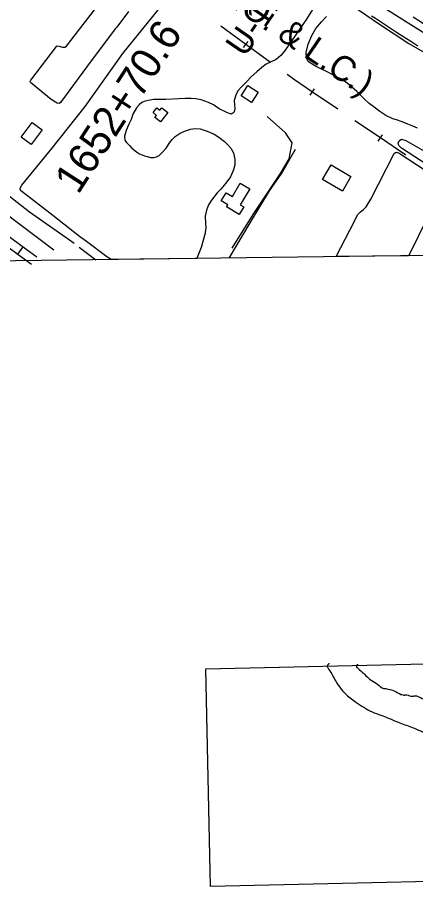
# Model space of a CAD drawing. Extents: x 3734862 to 3772949, y 391520 to 417239.
# Drawn here: x 3758594 to 3759905, y 395044 to 397909 of the extents above; entities that cross this region are included whole.
import ezdxf

# ---------------------------------------------------------------- set-up
doc = ezdxf.new("R2010")
doc.units = 0
for name, color, linetype in [('V-ANNO-NPLT', 7, 'Continuous'), ('V-BLDG-OTLN', 7, 'Continuous'), ('V-FLOD-BASE', 7, 'Continuous'), ('V-GRID-FRAM', 7, 'Continuous'), ('V-LEVE-TOET', 7, 'Continuous'), ('V-RAIL-IDEN', 7, 'Continuous'), ('V-RAIL-TRAK', 7, 'Continuous'), ('V-RIVR-EDGE', 7, 'Continuous'), ('V-RIVR-RANG-IDEN', 7, 'Continuous'), ('V-ROAD-CNTR', 7, 'Continuous'), ('V-SITE-VEGE', 7, 'Continuous'), ('V-SURV-IDEN', 7, 'Continuous'), ('V-SURV-LINE', 7, 'Continuous'), ('V-TOPO-SHOR', 7, 'Continuous')]:
    doc.layers.add(name, color=color, linetype=linetype)

msp = doc.modelspace()

# ---------------------------------------------------------------- linework, layer by layer
at = {"layer": 'V-ANNO-NPLT'}
for points in [[(3759229.9, 395044.4), (3759213.9, 395762.4), (3760468.2, 395790.9), (3760484.8, 395072.9)], [(3760484.8, 395072.9), (3759229.9, 395044.4)]]:
    msp.add_lwpolyline(points, dxfattribs=at)
for points in [[(3759613.6, 395771.7), (3759613.5, 395771.5), (3759614.4, 395768.6), (3759616.7, 395764.5), (3759628.7, 395745.7)], [(3759619.7, 395780.6), (3759619.6, 395778.6), (3759617.3, 395776.3), (3759615.2, 395774.6), (3759614.1, 395772.8), (3759613.6, 395771.7)], [(3759711.1, 395773.8), (3759710.8, 395773.6), (3759709.6, 395772.4), (3759709.9, 395770.6), (3759710.6, 395768.7), (3759711.5, 395767.1), (3759712.4, 395766.2)], [(3759713.9, 395777.5), (3759714.2, 395776.4), (3759713.8, 395775.7), (3759712.2, 395774.5), (3759711.1, 395773.8)], [(3759628.7, 395745.7), (3759651, 395707.3), (3759668.8, 395684.9), (3759702.3, 395656.6), (3759753.9, 395623.4)], [(3759712.1, 395766.5), (3759729, 395751.6), (3759745.8, 395735.6), (3759753.3, 395728.7), (3759775.6, 395715.1), (3759794.7, 395699.6), (3759799.7, 395697.8), (3759806.7, 395697), (3759815, 395695.7), (3759856.7, 395678.1)], [(3759856.7, 395678.1), (3759863.7, 395676.3), (3759869.7, 395675.9), (3759872.4, 395676.4), (3759889.1, 395672.4), (3759893.7, 395672), (3759898.3, 395672.5), (3759902.5, 395673), (3759907.6, 395673.1), (3759915.4, 395670.4), (3759939.1, 395661.9), (3759944.6, 395661.9), (3759953.9, 395658.3), (3759982.6, 395646.6)], [(3759753.9, 395623.4), (3759784.5, 395611.7), (3759797, 395607.2), (3759818.3, 395598.7), (3759852.6, 395584.2), (3759896.7, 395568.1), (3759932.4, 395552.3)]]:
    msp.add_spline(points, degree=3, dxfattribs=at)
at = {"layer": 'V-BLDG-OTLN'}
for points in [[(3759386.6, 397662.8), (3759364.8, 397628.6), (3759330.6, 397650.4), (3759352.4, 397684.5)], [(3759089.1, 397595.4), (3759065, 397564.8), (3759046.5, 397579.4), (3759052.1, 397586.4), (3759040.6, 397595.5), (3759053, 397611.2), (3759063, 397603.4), (3759069.1, 397611.1)], [(3758675.3, 397538.6), (3758639, 397489.9), (3758606.4, 397514.3), (3758642.7, 397563)], [(3759664.4, 397336.8), (3759598.6, 397374.9), (3759626.5, 397423.1), (3759692.3, 397384.9)], [(3759359, 397344.2), (3759327.9, 397291.9), (3759339.2, 397285.2), (3759324.3, 397260.2), (3759282.8, 397284.8), (3759287.1, 397292), (3759265.2, 397305), (3759280.9, 397331.5), (3759301.9, 397319), (3759327.9, 397362.7)]]:
    msp.add_lwpolyline(points, close=True, dxfattribs=at)
at = {"layer": 'V-FLOD-BASE'}
msp.add_lwpolyline([(3759946.6, 397878.8), (3759896.5, 397909.9)], dxfattribs=at)
at = {"layer": 'V-GRID-FRAM'}
msp.add_lwpolyline([(3738832.3, 415033.8), (3770599.2, 415447.4), (3770843.8, 397266.6), (3739061.1, 396852.8), (3738832.3, 415033.8)], dxfattribs=at)
at = {"layer": 'V-LEVE-TOET'}
msp.add_lwpolyline([(3759912.9, 397814.7), (3759889.3, 397829.4), (3759865.8, 397844.3), (3759842.4, 397859.4), (3759819.2, 397874.7), (3759796, 397890.1), (3759773, 397905.7), (3759759.6, 397913.2)], dxfattribs=at)
at = {"layer": 'V-RAIL-TRAK'}
for points in [[(3759345.8, 397820.3), (3759264.1, 397880.1)], [(3759338.5, 397810.2), (3759353.2, 397830.4)], [(3759427.6, 397760.6), (3759345.8, 397820.3)], [(3759565.4, 397663.2), (3759503.2, 397705.3), (3759482, 397720.7)], [(3759558.4, 397652.9), (3759572.4, 397673.6)], [(3759649.3, 397606.5), (3759565.4, 397663.2)], [(3759789.1, 397512.1), (3759705.2, 397568.8)], [(3759782.1, 397501.7), (3759796.1, 397522.4)], [(3759873, 397455.4), (3759869.1, 397458), (3759789.1, 397512.1)]]:
    msp.add_lwpolyline(points, dxfattribs=at)
at = {"layer": 'V-RIVR-EDGE'}
for points in [[(3755702.1, 404495.3), (3755757.2, 404470.8), (3755793.3, 404451.2), (3755852.5, 404424.4), (3755881.4, 404415.7), (3755906.2, 404404.4), (3755920.2, 404395.8), (3755948.7, 404379.4), (3755958.2, 404378.9), (3755969, 404378), (3755990.7, 404368.5), (3756022.8, 404350.3), (3756054.8, 404336.6), (3756079.7, 404323), (3756103.6, 404309.4), (3756144.2, 404288), (3756167.7, 404269), (3756188.9, 404253.6), (3756231.4, 404233.1), (3756271.6, 404217.2), (3756299.1, 404203.1), (3756403, 404163.5), (3756460.4, 404140.3), (3756508.7, 404114.9), (3756530.8, 404104), (3756588.2, 404078), (3756639.2, 404052.1), (3756694.3, 404019.5), (3756726.8, 403998.1), (3756735.8, 403989.1), (3756740.3, 403979.6), (3756740.3, 403973.2), (3756740.7, 403967.8), (3756747.5, 403960.5), (3756759.7, 403953.7), (3756786.3, 403941.5), (3756814.3, 403929.2), (3756864.5, 403904.6), (3756889.3, 403896), (3756899.7, 403897.3), (3756908.3, 403901.8), (3756919.2, 403901.3), (3756933.2, 403894.1), (3756945.8, 403892.7), (3756956.2, 403893.1), (3756962.1, 403897.2), (3756970.7, 403896.7), (3756978.4, 403894.4), (3756992.4, 403894.8), (3757002.8, 403897.5), (3757019.1, 403901.5), (3757027.7, 403901.5), (3757034, 403901.1), (3757036.3, 403896.5), (3757036.7, 403891.1), (3757038.5, 403883.4), (3757046.6, 403874.3), (3757060.6, 403866.2), (3757076.4, 403853.9), (3757104.4, 403831.2), (3757122.4, 403816.7), (3757145.5, 403804.5), (3757165.3, 403796.7), (3757181.6, 403787.2), (3757194.2, 403777.7), (3757213.6, 403765.4), (3757229.9, 403756.3), (3757251.6, 403745.9), (3757266.5, 403741.3), (3757283.2, 403734.5), (3757308.9, 403720.9), (3757360.4, 403694.1), (3757393.8, 403670.9), (3757430, 403657.3), (3757461.6, 403645.4), (3757505.4, 403628.1), (3757548.3, 403610.4), (3757591.7, 403587.2), (3757649.5, 403552.3), (3757711.8, 403512.8), (3757753.8, 403493.2), (3757766.9, 403487.8), (3757773.2, 403487.8), (3757785.9, 403494.1), (3757794.5, 403494), (3757803.5, 403489.5), (3757807.1, 403480.9), (3757810.6, 403456), (3757814.2, 403447.9), (3757826.4, 403437), (3757854.4, 403422.9), (3757930.3, 403373.9), (3757975.8, 403342.6), (3758005.2, 403323.5), (3758062.1, 403286.7), (3758092.3, 403263.6), (3758175.8, 403209.6), (3758234.5, 403169.2), (3758283.7, 403133.8), (3758328.8, 403103.4), (3758399.2, 403041.7), (3758421.8, 403023.1), (3758438.1, 403017.7), (3758463.8, 403017.6), (3758491.4, 403026.1), (3758504.5, 403022), (3758513.6, 403014.3), (3758514, 403006.2), (3758499.9, 402997.2), (3758498.1, 402989.9), (3758502.2, 402978.2), (3758510.7, 402969.6), (3758522, 402962.8), (3758545, 402948.7), (3758582.1, 402926.9), (3758650.2, 402878.8), (3758697.6, 402840.7), (3758721.5, 402820.3), (3758740.9, 402809.4), (3758782, 402784.9), (3758831.2, 402755.4), (3758902.1, 402711.8), (3758960.4, 402675.5), (3759018.6, 402634.6), (3759069.6, 402599.7), (3759134.6, 402553.4), (3759185.6, 402508.1), (3759223.5, 402478.1), (3759262.3, 402448.2), (3759321.4, 402402.4), (3759371.5, 402366.1), (3759431.5, 402323.4), (3759463.6, 402300.3), (3759488.9, 402281.7), (3759576.9, 402222.7), (3759627, 402186.8), (3759672.1, 402153.7), (3759778.2, 402087.4), (3759832.8, 402050.7), (3759873, 402019.4), (3759909.5, 401989.4), (3760050.8, 401883.7), (3760100, 401850.2), (3760145.6, 401819.3), (3760185.8, 401788), (3760211.9, 401766.7), (3760254.8, 401734.5), (3760285.5, 401709.1), (3760303.1, 401700.5), (3760325.3, 401691.4), (3760352.8, 401671.4), (3760391.1, 401641), (3760430.4, 401612), (3760461.6, 401590.2), (3760536.9, 401543), (3760583, 401510.8), (3760602.8, 401495.8), (3760629, 401477.2), (3760672.4, 401449.5), (3760711.2, 401426.8), (3760818.6, 401347.8), (3760872.3, 401310.6), (3760925.6, 401271.6), (3760948.6, 401251.7), (3761039.8, 401181.8), (3761107, 401135.5), (3761151.7, 401104.7), (3761172.9, 401093.3), (3761186, 401090.6), (3761199.2, 401092.8), (3761219.5, 401099.1), (3761228.1, 401099.5), (3761233.5, 401095.4), (3761236.7, 401087.7), (3761236.6, 401077.8), (3761228.5, 401063.8), (3761223, 401057.5), (3761223, 401049.3), (3761228.9, 401039.4), (3761242.4, 401026.7), (3761254.1, 401021.7), (3761266.8, 401018.5), (3761292.5, 401001.7), (3761317.3, 400980.4), (3761342.1, 400955.4), (3761463.1, 400853.4), (3761510, 400812.1), (3761550.2, 400777.7), (3761585.3, 400746.8), (3761681.5, 400674.3), (3761756.4, 400618.9), (3761817.8, 400572.2), (3761878.3, 400530.4), (3761996.5, 400436.5), (3762057.4, 400389.8), (3762104.8, 400352.6), (3762156.3, 400313.2), (3762204.5, 400277.3), (3762245.2, 400247.8), (3762291.6, 400210.2), (3762325.9, 400182.1), (3762356.2, 400159.8), (3762404, 400123.6), (3762432.9, 400101.3), (3762455.5, 400091.3), (3762473.5, 400075.9), (3762512.3, 400044.2), (3762551.6, 400012.4), (3762593.6, 399983.8), (3762620.2, 399963.4), (3762661.7, 399937.1), (3762686.6, 399919.8), (3762793.1, 399841.3), (3762834.6, 399812.8), (3762873.4, 399790.1), (3762923.1, 399758.3), (3762957, 399737.4), (3762984, 399721.5), (3763024.2, 399693.4), (3763075.2, 399657.5), (3763115.9, 399633.9), (3763172.8, 399601.2), (3763228.7, 399568.5), (3763285.2, 399533.6), (3763344.3, 399494.1), (3763398.5, 399455.1), (3763444.1, 399421), (3763484.7, 399391.1), (3763603.4, 399303.1), (3763654.8, 399261.8), (3763661.1, 399259.5), (3763667, 399254.5), (3763672, 399245), (3763696.3, 399224.2), (3763722.9, 399200.1), (3763745.5, 399180.2), (3763818.1, 399117.2), (3763841.6, 399099.5), (3763852.4, 399092.2), (3763858.8, 399084.1), (3763875, 399067.3), (3763898, 399046), (3763924.6, 399023.8), (3763949, 399007.9), (3763970.2, 398987.5), (3764004, 398952.6), (3764028.4, 398926.7), (3764056.8, 398899.5), (3764092.9, 398862.4), (3764130.8, 398826.1), (3764147, 398811.6), (3764152.9, 398799.8), (3764162.3, 398783.5), (3764173.6, 398768.6), (3764186.7, 398757.2), (3764206.1, 398746.3), (3764226.9, 398742.2), (3764246.3, 398733.6), (3764269.3, 398717.7), (3764284.2, 398703.2), (3764301.8, 398691.8), (3764323, 398678.2), (3764345.1, 398661), (3764412.4, 398596.6), (3764457, 398559.9), (3764502.6, 398522.7), (3764538.3, 398497.7), (3764566.3, 398486.4), (3764583.9, 398484.5), (3764604.2, 398486.3), (3764616.5, 398486.2), (3764626.4, 398481.7), (3764630.9, 398474.4), (3764636.3, 398461.3), (3764634.9, 398450), (3764631.7, 398441.4), (3764633.1, 398434.7), (3764636.2, 398430.1), (3764643.9, 398425.6), (3764661.1, 398421.5), (3764685.4, 398409.2), (3764715.2, 398382), (3764745.4, 398356.1), (3764793.3, 398328), (3764844.3, 398292.6), (3764885.8, 398258.1), (3764918.8, 398234.5), (3764992.8, 398187.8), (3765058.3, 398144.2), (3765088.1, 398128.3), (3765140.9, 398100.2), (3765168.9, 398079.7), (3765193.7, 398061.6), (3765246.1, 398042), (3765282.2, 398018.4), (3765309.7, 397989.4), (3765340, 397955.4), (3765361.1, 397933.7), (3765382.3, 397911.9), (3765434.7, 397867.9), (3765477.6, 397838.4), (3765508.7, 397823.9), (3765545.3, 397801.2), (3765575.5, 397778), (3765617.5, 397749.9), (3765653.6, 397726.3), (3765681.6, 397710), (3765727.2, 397684.5), (3765762, 397660), (3765771.9, 397659.5), (3765788.2, 397660), (3765793.6, 397658.1), (3765793.6, 397653.6), (3765785.5, 397648.7), (3765785.5, 397645.5), (3765790.9, 397632.8), (3765800.3, 397623.8), (3765814.8, 397612.9), (3765831.9, 397605.6), (3765847.3, 397603.3), (3765858.1, 397598.7), (3765865.8, 397593.3), (3765888.8, 397577), (3765908.7, 397561.5), (3765918.2, 397548.4), (3765919.5, 397542.1), (3765921.3, 397536.2), (3765926.7, 397533.5), (3765933, 397534.4), (3765940.7, 397533.4), (3765944.8, 397530.3), (3765957, 397519.4), (3765987.7, 397499.9), (3766024.7, 397468.1), (3766059.4, 397438.2), (3766085.1, 397413.3), (3766102.7, 397400.1), (3766131.6, 397377.4), (3766172.7, 397350.2), (3766210.6, 397318.9), (3766264.3, 397285.3), (3766306.8, 397260.8), (3766362.7, 397220.8), (3766381.1, 397208.5)], [(3759040.2, 398931), (3759064.4, 398911.6), (3759092.7, 398888), (3759114.1, 398872.6), (3759137.5, 398853.2), (3759176.6, 398819.1), (3759210.1, 398787.5), (3759239.5, 398759.9), (3759277.5, 398727.5), (3759309.7, 398699.9), (3759337.6, 398671.9), (3759369.4, 398643.1), (3759396.1, 398618.8), (3759421.9, 398601.3), (3759451, 398585.1), (3759470, 398572.9), (3759488.5, 398560.3), (3759524.5, 398538.4), (3759537.8, 398529.5), (3759550.3, 398519.7), (3759565.6, 398507.6), (3759581, 398502.3), (3759593.9, 398497), (3759611.3, 398487.7), (3759623, 398478.7), (3759635.9, 398467.4), (3759641.5, 398462.1), (3759650.4, 398457.2), (3759666.6, 398449.9), (3759678.7, 398445.4), (3759700.9, 398434.5), (3759717.9, 398425.1), (3759741.3, 398407.7), (3759774.8, 398379.3), (3759806.3, 398348.9), (3759828.8, 398324.6), (3759851.8, 398297.4), (3759868.4, 398279.2), (3759894.6, 398256.9), (3759920, 398241.4), (3759935.4, 398232.1), (3759976.1, 398198.4), (3760003.6, 398178.6), (3760032.6, 398160.7), (3760062.5, 398142.8), (3760085.1, 398133.5), (3760112.2, 398118.8), (3760130.8, 398103.8), (3760179.6, 398061.3), (3760208.2, 398036.5), (3760224, 398020.3), (3760241.3, 398004.5), (3760263.9, 397987.4), (3760285.7, 397973.2), (3760305.5, 397959.8), (3760330.9, 397942.4), (3760351.5, 397924.6), (3760376.1, 397905.5), (3760414.1, 397881.5), (3760443.5, 397862.5), (3760477.5, 397840.1), (3760515.8, 397813.4), (3760558.2, 397782.9), (3760581.2, 397763.9), (3760591.7, 397757), (3760606.6, 397747.6), (3760619.5, 397738.7), (3760636.9, 397726.9), (3760667.6, 397705), (3760693.8, 397687.2), (3760721.7, 397667.3), (3760754.8, 397642.1), (3760786.7, 397617), (3760803.2, 397604), (3760832.7, 397585.7), (3760863, 397569.5), (3760907, 397538.6), (3760923.5, 397527.3), (3760924.3, 397525.6), (3760925.9, 397522.8), (3760928.3, 397518), (3760932.8, 397516.3), (3760937.2, 397515.9), (3760941.3, 397515.9), (3760946.9, 397512.2), (3760950.6, 397506.6), (3760957.4, 397502.1), (3760969.9, 397494.8), (3760984.1, 397484.2), (3760999.4, 397475.7), (3761016.4, 397468.4), (3761026.5, 397461.5), (3761039.4, 397454.6), (3761058.4, 397440.4), (3761080.2, 397425.8), (3761107.6, 397409.5), (3761155.7, 397381.9), (3761196.1, 397360), (3761222.7, 397347), (3761261.9, 397330.7), (3761289, 397320.1), (3761321.7, 397305.1), (3761356.4, 397287.2), (3761414.5, 397252.7), (3761462.2, 397221.8), (3761502.2, 397194.2), (3761522.3, 397182.5), (3761561.9, 397158.1), (3761582.6, 397146)]]:
    msp.add_spline(points, degree=3, dxfattribs=at)
at = {"layer": 'V-ROAD-CNTR'}
msp.add_line((3758612, 397153.4), (3758594.3, 397129.2), dxfattribs=at)
for points in [[(3757586.2, 397981.9), (3757749.2, 397861), (3758032, 397647.9), (3758284.1, 397463.9), (3758547.8, 397268.2), (3758713.4, 397143.2)], [(3757474.7, 397960.2), (3757598.9, 397866), (3757722.2, 397774), (3757882.1, 397656.5), (3758045.4, 397536.1), (3758172, 397442.5), (3758275.3, 397366.4), (3758429.6, 397250.5), (3758445.4, 397238.9), (3758608.7, 397118.6), (3758640.5, 397095.7)], [(3759301.3, 397148.2), (3759370, 397259.8), (3759459.8, 397395.3), (3759488.8, 397443.7), (3759498.3, 397496), (3759476.3, 397528.6), (3759416.8, 397582.2)], [(3759291.5, 397116.2), (3759360.4, 397232.6), (3759424.2, 397337.7), (3759464.7, 397396.4), (3759509.2, 397475.1)], [(3758477.4, 397252.5), (3758626.4, 397142.9), (3758658.1, 397120)]]:
    msp.add_lwpolyline(points, dxfattribs=at)
at = {"layer": 'V-SITE-VEGE'}
for p, q in [((3758940.7, 397790.4), (3759072.9, 397953.4)), ((3759588, 397971.5), (3759546.3, 397903.9)), ((3759546.3, 397903.9), (3759472.9, 397798)), ((3758816.8, 397616.2), (3758940.7, 397790.4)), ((3759461.7, 397783.3), (3759446.4, 397770.9)), ((3759472.9, 397798), (3759461.7, 397783.3)), ((3759413.5, 397755), (3759398.2, 397743.8)), ((3759429.4, 397762.6), (3759413.5, 397755)), ((3759446.4, 397770.9), (3759429.4, 397762.6)), ((3759381.8, 397729.7), (3759363.6, 397713.2)), ((3759398.2, 397743.8), (3759381.8, 397729.7)), ((3759348.3, 397697.3), (3759341.3, 397690.2)), ((3759363.6, 397713.2), (3759348.3, 397697.3)), ((3759321.3, 397667.9), (3759314.2, 397656.1)), ((3759330.7, 397679), (3759321.3, 397667.9)), ((3759341.3, 397690.2), (3759330.7, 397679)), ((3759024.9, 397635.2), (3759010.8, 397632.3)), ((3759043.2, 397638.2), (3759024.9, 397635.2)), ((3759063.2, 397638.8), (3759043.2, 397638.2)), ((3759082.6, 397638.8), (3759063.2, 397638.8)), ((3759124.9, 397640.6), (3759082.6, 397638.8)), ((3759146.7, 397642.4), (3759124.9, 397640.6)), ((3759165.5, 397642.4), (3759146.7, 397642.4)), ((3759181.9, 397641.3), (3759165.5, 397642.4)), ((3759198.4, 397637.2), (3759181.9, 397641.3)), ((3759223.1, 397629), (3759198.4, 397637.2)), ((3759314.2, 397656.1), (3759307.2, 397634.9)), ((3759307.2, 397634.9), (3759309, 397619.6)), ((3758707, 397476.8), (3758816.8, 397616.2)), ((3758985.6, 397611.1), (3758974.4, 397589.9)), ((3758995, 397621.1), (3758985.6, 397611.1)), ((3759003.2, 397628.8), (3758995, 397621.1)), ((3759010.8, 397632.3), (3759003.2, 397628.8)), ((3759239.6, 397621.3), (3759223.1, 397629)), ((3759258.4, 397608.4), (3759239.6, 397621.3)), ((3759285.5, 397594.3), (3759258.4, 397608.4)), ((3759309, 397619.6), (3759310.2, 397609.6)), ((3759310.2, 397609.6), (3759309, 397603.2)), ((3758974.4, 397589.9), (3758968, 397572.3)), ((3759297.8, 397590.8), (3759285.5, 397594.3)), ((3759303.1, 397593.2), (3759297.8, 397590.8)), ((3759307.2, 397598.5), (3759303.1, 397593.2)), ((3759309, 397603.2), (3759307.2, 397598.5)), ((3758960.3, 397557.6), (3758952.1, 397536.4)), ((3758968, 397572.3), (3758960.3, 397557.6)), ((3758952.1, 397536.4), (3758946.8, 397517.6)), ((3759113.3, 397516.5), (3759129.7, 397528.3)), ((3759129.7, 397528.3), (3759147.9, 397536)), ((3759147.9, 397536), (3759163.8, 397540.7)), ((3759163.8, 397540.7), (3759179.7, 397543.7)), ((3759179.7, 397543.7), (3759196.1, 397541.9)), ((3759196.1, 397541.9), (3759219.1, 397534.3)), ((3759219.1, 397534.3), (3759242, 397524.3)), ((3759242, 397524.3), (3759257.3, 397514.9)), ((3758946.8, 397517.6), (3758948, 397505.2)), ((3758948, 397505.2), (3758952.7, 397497)), ((3758952.7, 397497), (3758962.7, 397487)), ((3759083.3, 397478.3), (3759095.6, 397497.1)), ((3759095.6, 397497.1), (3759103.3, 397507.1)), ((3759103.3, 397507.1), (3759113.3, 397516.5)), ((3759257.3, 397514.9), (3759275.6, 397500.8)), ((3759275.6, 397500.8), (3759287.3, 397489.7)), ((3758608.3, 397356.7), (3758707, 397476.8)), ((3758962.7, 397487), (3758970.4, 397478.2)), ((3758970.4, 397478.2), (3758986.3, 397465.8)), ((3758986.3, 397465.8), (3758995.7, 397459.4)), ((3759060.4, 397454.2), (3759070.4, 397463.6)), ((3759070.4, 397463.6), (3759083.3, 397478.3)), ((3759287.3, 397489.7), (3759296.8, 397478.5)), ((3759296.8, 397478.5), (3759305, 397462.6)), ((3759305, 397462.6), (3759310.3, 397440.9)), ((3759834.2, 397460.3), (3759839.2, 397464.6)), ((3759839.2, 397464.6), (3759843.2, 397465)), ((3759843.2, 397465), (3759851.4, 397461.9)), ((3759851.4, 397461.9), (3759974.3, 397380.6)), ((3758995.7, 397459.4), (3759012.8, 397453.5)), ((3759012.8, 397453.5), (3759021.6, 397450.6)), ((3759021.6, 397450.6), (3759031.6, 397447.7)), ((3759031.6, 397447.7), (3759042.8, 397447.1)), ((3759042.8, 397447.1), (3759052.2, 397450)), ((3759052.2, 397450), (3759060.4, 397454.2)), ((3759310.3, 397440.9), (3759310.3, 397423.2)), ((3759758, 397310), (3759834.2, 397460.3)), ((3759305.7, 397406.8), (3759295.1, 397383.8)), ((3759310.3, 397423.2), (3759305.7, 397406.8)), ((3759295.1, 397383.8), (3759280.4, 397363.2)), ((3758603, 397342), (3758604.2, 397348.5)), ((3758604.2, 397348.5), (3758608.3, 397356.7)), ((3759280.4, 397363.2), (3759263.4, 397343.2)), ((3758606.5, 397337.3), (3758603, 397342)), ((3758608.3, 397335.5), (3758606.5, 397337.3)), ((3758710.1, 397256.2), (3758608.3, 397335.5)), ((3759251.6, 397331.4), (3759232.8, 397307.3)), ((3759263.4, 397343.2), (3759251.6, 397331.4)), ((3759222.8, 397291.4), (3759216.4, 397273.8)), ((3759232.8, 397307.3), (3759222.8, 397291.4)), ((3759742.4, 397285), (3759758, 397310)), ((3759216.4, 397273.8), (3759212.3, 397254.4)), ((3759713.9, 397258.7), (3759718.2, 397263.4)), ((3759718.2, 397263.4), (3759723.6, 397268.1)), ((3759723.6, 397268.1), (3759732.2, 397274.8)), ((3759732.2, 397274.8), (3759742.4, 397285)), ((3758797.8, 397187.5), (3758710.1, 397256.2)), ((3759212.3, 397254.4), (3759212.9, 397231.4)), ((3759643.3, 397120.8), (3759703.7, 397238)), ((3759703.7, 397238), (3759713.9, 397258.7)), ((3759212.9, 397210.3), (3759211.8, 397197.9)), ((3759212.9, 397231.4), (3759214.1, 397214.4)), ((3759214.1, 397214.4), (3759212.9, 397210.3)), ((3759931.4, 397223.4), (3759897, 397153.3)), ((3758821.1, 397170.5), (3758797.8, 397187.5)), ((3759211.8, 397197.9), (3759198.9, 397151.4)), ((3758888.4, 397120), (3758821.1, 397170.5)), ((3759198.9, 397151.4), (3759186, 397118.5)), ((3759897, 397153.3), (3759881.3, 397123.9)), ((3758902.2, 397111.1), (3758888.4, 397120)), ((3759186, 397118.5), (3759184.7, 397114.8)), ((3759881.3, 397123.9), (3759643.3, 397120.8)), ((3759184.7, 397114.8), (3758902.2, 397111.1))]:
    msp.add_line(p, q, dxfattribs=at)
for points in [[(3758959.9, 397928.9), (3758921.6, 397877.2), (3758916.1, 397871.8), (3758824.7, 397749.6), (3758736, 397629.1), (3758730.9, 397625.9), (3758724.3, 397626.7), (3758704.7, 397638.4), (3758636.6, 397694.3), (3758636.2, 397697.8), (3758637.8, 397702.9), (3758722.2, 397813.3), (3758725.3, 397816), (3758731.1, 397814.9), (3758742.1, 397811.7), (3758750.3, 397811), (3758755.8, 397814.1), (3758783.9, 397851.7), (3758893.7, 397994.2)], [(3759696.1, 397949), (3759785.9, 397886.9), (3759882.7, 397823.7), (3760040.6, 397731.7)], [(3759911.7, 397544.5), (3759895.9, 397551), (3759880, 397557.4), (3759861.3, 397565.6), (3759842.5, 397572), (3759830.2, 397574.9), (3759807.3, 397586.1), (3759787.3, 397598.9), (3759768.5, 397613.6), (3759752.1, 397625.9), (3759735.7, 397641.1), (3759711, 397664.6), (3759685.2, 397688.6), (3759665.8, 397703.2), (3759640, 397716.1), (3759615.9, 397728.4), (3759591.3, 397740.7), (3759575.4, 397748.3), (3759564.3, 397754.7), (3759553.7, 397763), (3759549.6, 397768.2), (3759546.1, 397775.3), (3759544.9, 397794), (3759551.3, 397821), (3759563, 397849.8), (3759576.5, 397872.6), (3759595.2, 397894.4), (3759611.7, 397912)], [(3760009, 397380.5), (3759858.9, 397478.6), (3759850.1, 397486.8), (3759847.2, 397494.4), (3759850.7, 397502.9), (3759858.3, 397507.6), (3759873, 397504.1), (3759934.8, 397468.9)]]:
    msp.add_lwpolyline(points, dxfattribs=at)
at = {"layer": 'V-SURV-LINE'}
msp.add_lwpolyline([(3760940.7, 397222.9), (3759277.5, 398270.4)], dxfattribs=at)
at = {"layer": 'V-TOPO-SHOR'}
for points in [[(3758520.7, 397356.7), (3758633.6, 397269), (3758765, 397176), (3758780.7, 397165.1)], [(3758797.1, 397152.2), (3758852.2, 397110.5)]]:
    msp.add_lwpolyline(points, dxfattribs=at)

# ---------------------------------------------------------------- texts
at = {"layer": 'V-RAIL-IDEN'}
msp.add_text('MO. PAC.    (N.O. & L.C.)', height=83, rotation=325.6769, dxfattribs=at).set_placement((3758687.3, 398359.8))
at = {"layer": 'V-RIVR-RANG-IDEN'}
msp.add_text('U-110', height=83, rotation=55.6133, dxfattribs=at).set_placement((3759342.3, 397774.7))
at = {"layer": 'V-SURV-IDEN'}
msp.add_text('1652+70.6', height=100, rotation=57.0442, dxfattribs=at).set_placement((3758793.8, 397322.8))

doc.saveas('drawing.dxf')
